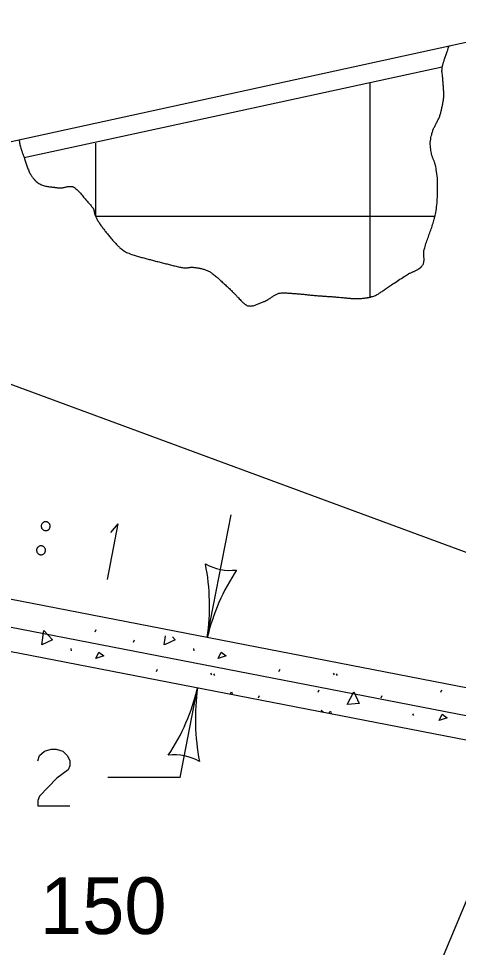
# Model space of a CAD drawing. Extents: x 49991.4 to 50043, y 49987.6 to 50011.4.
# Drawn here: x 50038.895 to 50039.361, y 49997.154 to 49998.137 of the extents above; entities that cross this region are included whole.
import ezdxf

# ---------------------------------------------------------------- set-up
doc = ezdxf.new("R2010")
doc.units = 0
for name, color, linetype in [('Level 1', 7, 'Continuous'), ('Level 2', 7, 'Continuous'), ('Level 3', 7, 'Continuous')]:
    doc.layers.add(name, color=color, linetype=linetype)

msp = doc.modelspace()

# ---------------------------------------------------------------- linework, layer by layer
at = {"layer": 'Level 1'}
for p, q in [((50038.66184, 49997.95822), (50039.48364, 49998.13732)), ((50039.34353, 49998.08582), (50038.90144, 49997.98982)), ((50039.26714, 49998.06922), (50039.26714, 49997.84252)), ((50038.97674, 49998.00562), (50038.97674, 49997.92812)), ((50038.97674, 49997.92812), (50039.33574, 49997.92812)), ((50039.48364, 49997.52972), (50038.58314, 49997.86252)), ((50039.48364, 49997.40692), (50038.66184, 49997.56632)), ((50038.61974, 49997.54532), (50039.48364, 49997.3773)), ((50038.77334, 49997.48952), (50039.37054, 49997.37372)), ((50038.91984, 49997.47452), (50038.92194, 49997.48982)), ((50038.92194, 49997.48982), (50038.93144, 49997.47992)), ((50038.97654, 49997.48822), (50038.97754, 49997.49062)), ((50038.93144, 49997.47992), (50038.92004, 49997.47462)), ((50039.01704, 49997.47732), (50039.01804, 49997.47972)), ((50039.04944, 49997.47452), (50039.05074, 49997.48422)), ((50039.06104, 49997.47992), (50039.04964, 49997.47462)), ((50039.05814, 49997.48302), (50039.06104, 49997.47992)), ((50038.95074, 49997.47062), (50038.95104, 49997.46822)), ((50038.97704, 49997.46022), (50038.98024, 49997.46692)), ((50038.98024, 49997.46692), (50038.98554, 49997.46292)), ((50039.08034, 49997.47062), (50039.08064, 49997.46822)), ((50039.10664, 49997.46022), (50039.10984, 49997.46692)), ((50039.10984, 49997.46692), (50039.11514, 49997.46292)), ((50038.98554, 49997.46292), (50038.97704, 49997.46022)), ((50039.11514, 49997.46292), (50039.10664, 49997.46022)), ((50039.04124, 49997.44642), (50039.04234, 49997.44882)), ((50039.17084, 49997.44642), (50039.17194, 49997.44882)), ((50039.09854, 49997.44442), (50039.09964, 49997.44282)), ((50039.10164, 49997.44382), (50039.10264, 49997.44222)), ((50039.22814, 49997.44442), (50039.22924, 49997.44282)), ((50039.23124, 49997.44382), (50039.23224, 49997.44222)), ((50039.21244, 49997.42462), (50039.21344, 49997.42702)), ((50039.34204, 49997.42462), (50039.34314, 49997.42702)), ((50039.11924, 49997.42242), (50039.12054, 49997.42492)), ((50039.12054, 49997.42492), (50039.12184, 49997.42192)), ((50039.14924, 49997.41852), (50039.15034, 49997.42092)), ((50039.24294, 49997.41132), (50039.25014, 49997.42492)), ((50039.25014, 49997.42492), (50039.25574, 49997.41242)), ((50039.27894, 49997.41852), (50039.27994, 49997.42092)), ((50039.25574, 49997.41242), (50039.24324, 49997.41132)), ((50039.21564, 49997.40492), (50039.21584, 49997.40372)), ((50039.21764, 49997.40332), (50039.21564, 49997.40492)), ((50039.31224, 49997.40152), (50039.31324, 49997.39992)), ((50039.34014, 49997.39452), (50039.34334, 49997.40122)), ((50039.34864, 49997.39722), (50039.34014, 49997.39452)), ((50039.34334, 49997.40122), (50039.34864, 49997.39722))]:
    msp.add_line(p, q, dxfattribs=at)
msp.add_arc((50039.22513, 49997.40249), 0.00126, 318.78601, 199.26618, dxfattribs=at)
msp.add_open_spline([(50038.89596, 49998.00924), (50038.89625, 49998.00747), (50038.89655, 49998.00569), (50038.89684, 49998.00392), (50038.89725, 49998.00149), (50038.89796, 49997.99911), (50038.89882, 49997.9968), (50038.89926, 49997.99564), (50038.8997, 49997.99448), (50038.90013, 49997.99331), (50038.90057, 49997.99215), (50038.90101, 49997.99099), (50038.90144, 49997.98982), (50038.90222, 49997.98774), (50038.90282, 49997.9856), (50038.90353, 49997.98349), (50038.90423, 49997.98142), (50038.90496, 49997.97936), (50038.90572, 49997.9773), (50038.9065, 49997.97521), (50038.90754, 49997.97324), (50038.90872, 49997.97134), (50038.90934, 49997.97034), (50038.91001, 49997.96939), (50038.91075, 49997.96848), (50038.91113, 49997.96801), (50038.91153, 49997.96755), (50038.91193, 49997.96709), (50038.91235, 49997.96661), (50038.91279, 49997.96616), (50038.91324, 49997.96572), (50038.91488, 49997.96414), (50038.91671, 49997.96286), (50038.91879, 49997.96187), (50038.92074, 49997.96093), (50038.92274, 49997.96027), (50038.92484, 49997.95993), (50038.92693, 49997.95959), (50038.92903, 49997.95926), (50038.93114, 49997.95901), (50038.93219, 49997.95889), (50038.93325, 49997.95878), (50038.93431, 49997.95866), (50038.93535, 49997.95854), (50038.9364, 49997.95834), (50038.93744, 49997.95822), (50038.93893, 49997.95805), (50038.94044, 49997.95816), (50038.94192, 49997.95837), (50038.94349, 49997.95858), (50038.945, 49997.95907), (50038.94655, 49997.95932), (50038.94802, 49997.95956), (50038.94952, 49997.95971), (50038.951, 49997.95973), (50038.9517, 49997.95973), (50038.95238, 49997.95956), (50038.95306, 49997.9593), (50038.95376, 49997.95903), (50038.95439, 49997.9587), (50038.95494, 49997.95822), (50038.95704, 49997.9564), (50038.95899, 49997.95454), (50038.96076, 49997.95246), (50038.9625, 49997.95042), (50038.96419, 49997.94835), (50038.96594, 49997.94632), (50038.9673, 49997.94475), (50038.96867, 49997.9432), (50038.97003, 49997.94164), (50038.97139, 49997.94008), (50038.97268, 49997.93848), (50038.97394, 49997.93682), (50038.9744, 49997.93622), (50038.97475, 49997.93554), (50038.97496, 49997.93481), (50038.97516, 49997.93407), (50038.97533, 49997.93332), (50038.9755, 49997.93257), (50038.97566, 49997.93181), (50038.97579, 49997.93104), (50038.97596, 49997.93028), (50038.97613, 49997.92953), (50038.9764, 49997.92881), (50038.97674, 49997.92812), (50038.97857, 49997.92442), (50038.98068, 49997.92098), (50038.98307, 49997.91765), (50038.9855, 49997.91428), (50038.988, 49997.91102), (50038.99064, 49997.90782), (50038.99387, 49997.9039), (50038.99724, 49997.90018), (50039.00081, 49997.89654), (50039.00255, 49997.89478), (50039.00444, 49997.89325), (50039.00652, 49997.89187), (50039.00858, 49997.8905), (50039.01072, 49997.88932), (50039.01304, 49997.88852), (50039.01754, 49997.88697), (50039.02204, 49997.88552), (50039.02663, 49997.88431), (50039.0312, 49997.88311), (50039.03577, 49997.8819), (50039.04034, 49997.88072), (50039.04517, 49997.87948), (50039.04999, 49997.87824), (50039.05482, 49997.87701), (50039.05964, 49997.87578), (50039.06443, 49997.87467), (50039.06934, 49997.87362), (50039.07021, 49997.87344), (50039.07109, 49997.87336), (50039.07196, 49997.87344), (50039.07285, 49997.87352), (50039.07374, 49997.87362), (50039.07462, 49997.87374), (50039.07551, 49997.87385), (50039.0764, 49997.874), (50039.07729, 49997.8741), (50039.07817, 49997.8742), (50039.07906, 49997.87419), (50039.07994, 49997.87412), (50039.08172, 49997.87398), (50039.08347, 49997.8737), (50039.08523, 49997.87341), (50039.087, 49997.87311), (50039.08873, 49997.87275), (50039.09046, 49997.87226), (50039.09393, 49997.87127), (50039.09726, 49997.86982), (50039.10014, 49997.86762), (50039.10392, 49997.86474), (50039.10743, 49997.86173), (50039.11086, 49997.85853), (50039.11421, 49997.85541), (50039.11757, 49997.85232), (50039.12084, 49997.84912), (50039.12206, 49997.84793), (50039.12327, 49997.84673), (50039.12445, 49997.8455), (50039.12565, 49997.84427), (50039.12677, 49997.84297), (50039.12795, 49997.84173), (50039.12971, 49997.83987), (50039.13149, 49997.83805), (50039.13339, 49997.83633), (50039.1337, 49997.83604), (50039.13403, 49997.83578), (50039.13435, 49997.83551), (50039.13468, 49997.83524), (50039.13499, 49997.83498), (50039.13534, 49997.83472), (50039.13671, 49997.83373), (50039.13838, 49997.83323), (50039.13997, 49997.83316), (50039.14173, 49997.83309), (50039.14359, 49997.83338), (50039.1453, 49997.834), (50039.14893, 49997.83533), (50039.15244, 49997.83668), (50039.15594, 49997.83822), (50039.15668, 49997.83854), (50039.15741, 49997.83885), (50039.15811, 49997.83923), (50039.15884, 49997.83961), (50039.15953, 49997.84005), (50039.16022, 49997.84051), (50039.16163, 49997.84143), (50039.16296, 49997.84244), (50039.16436, 49997.84338), (50039.16572, 49997.84429), (50039.16707, 49997.84511), (50039.16859, 49997.84585), (50039.17004, 49997.84655), (50039.17159, 49997.8469), (50039.17314, 49997.84692), (50039.17713, 49997.84697), (50039.18113, 49997.84688), (50039.1851, 49997.84655), (50039.18909, 49997.84621), (50039.19308, 49997.84589), (50039.19707, 49997.84551), (50039.20107, 49997.84512), (50039.20505, 49997.84463), (50039.20905, 49997.8443), (50039.21305, 49997.84397), (50039.21705, 49997.8437), (50039.22104, 49997.84342), (50039.22296, 49997.84329), (50039.22489, 49997.84322), (50039.2268, 49997.84304), (50039.22873, 49997.84286), (50039.23065, 49997.84269), (50039.23258, 49997.84251), (50039.23643, 49997.84215), (50039.24028, 49997.84179), (50039.24413, 49997.84144), (50039.24796, 49997.84108), (50039.25183, 49997.84104), (50039.25567, 49997.84113), (50039.25759, 49997.84118), (50039.2595, 49997.84132), (50039.26142, 49997.84156), (50039.26238, 49997.84168), (50039.26333, 49997.8418), (50039.26428, 49997.84197), (50039.26476, 49997.84205), (50039.26524, 49997.84214), (50039.26571, 49997.84222), (50039.26619, 49997.84231), (50039.26667, 49997.84241), (50039.26714, 49997.84252), (50039.27108, 49997.84346), (50039.27481, 49997.84525), (50039.27819, 49997.84749), (50039.28162, 49997.84976), (50039.28493, 49997.85215), (50039.28834, 49997.85442), (50039.29435, 49997.85842), (50039.30033, 49997.86245), (50039.30644, 49997.86632), (50039.30768, 49997.8671), (50039.30899, 49997.86775), (50039.31032, 49997.86837), (50039.31165, 49997.869), (50039.31302, 49997.8695), (50039.31436, 49997.87012), (50039.3157, 49997.87074), (50039.31701, 49997.87139), (50039.31829, 49997.87214), (50039.31894, 49997.87252), (50039.31954, 49997.87296), (50039.32013, 49997.87344), (50039.32043, 49997.87368), (50039.32072, 49997.87393), (50039.32101, 49997.87419), (50039.3213, 49997.87445), (50039.32157, 49997.87472), (50039.32184, 49997.87502), (50039.32289, 49997.8762), (50039.32366, 49997.87758), (50039.32396, 49997.87912), (50039.32425, 49997.88068), (50039.32432, 49997.88223), (50039.32427, 49997.8838), (50039.32423, 49997.88542), (50039.32407, 49997.88704), (50039.32405, 49997.88867), (50039.32404, 49997.88946), (50039.32406, 49997.89025), (50039.32413, 49997.89104), (50039.3242, 49997.89182), (50039.32432, 49997.89258), (50039.32454, 49997.89332), (50039.3254, 49997.89624), (50039.32631, 49997.89912), (50039.32733, 49997.90197), (50039.32834, 49997.90484), (50039.32939, 49997.9077), (50039.3304, 49997.91057), (50039.33142, 49997.91345), (50039.33238, 49997.91634), (50039.33335, 49997.91924), (50039.33432, 49997.92215), (50039.33506, 49997.92509), (50039.33574, 49997.92812), (50039.33755, 49997.93611), (50039.33827, 49997.94417), (50039.33854, 49997.95222), (50039.33885, 49997.9615), (50039.33834, 49997.97085), (50039.33674, 49997.98012), (50039.33651, 49997.98146), (50039.33625, 49997.98278), (50039.33579, 49997.98405), (50039.33532, 49997.98532), (50039.33485, 49997.9866), (50039.33437, 49997.98787), (50039.3339, 49997.98914), (50039.33342, 49997.9904), (50039.33295, 49997.99167), (50039.33248, 49997.99291), (50039.33218, 49997.99422), (50039.33194, 49997.99552), (50039.33071, 49998.00238), (50039.33107, 49998.00969), (50039.33294, 49998.01652), (50039.33343, 49998.01829), (50039.33401, 49998.02001), (50039.33482, 49998.02163), (50039.33565, 49998.02327), (50039.33648, 49998.0249), (50039.33731, 49998.02653), (50039.33813, 49998.02817), (50039.33896, 49998.02981), (50039.33978, 49998.03145), (50039.3406, 49998.03309), (50039.34116, 49998.03485), (50039.34164, 49998.03662), (50039.34216, 49998.03851), (50039.34261, 49998.04041), (50039.34305, 49998.04231), (50039.34349, 49998.04421), (50039.34391, 49998.04609), (50039.34426, 49998.04802), (50039.34497, 49998.05185), (50039.34534, 49998.05569), (50039.34514, 49998.05952), (50039.34492, 49998.06375), (50039.34452, 49998.06799), (50039.34424, 49998.07222), (50039.34395, 49998.07678), (50039.34304, 49998.08138), (50039.34354, 49998.08592), (50039.3436, 49998.08641), (50039.34378, 49998.08689), (50039.34391, 49998.08737), (50039.34404, 49998.08785), (50039.34417, 49998.08833), (50039.3443, 49998.0888), (50039.34457, 49998.08976), (50039.34484, 49998.09071), (50039.34514, 49998.09166), (50039.34574, 49998.09354), (50039.34637, 49998.09542), (50039.347, 49998.09729), (50039.34825, 49998.10099), (50039.34959, 49998.10466), (50039.35079, 49998.10837)], degree=3, dxfattribs=at)
at = {"layer": 'Level 2'}
for q in [(50038.98904, 49997.54357), (50038.99271, 49997.5934)]:
    msp.add_line((50039.00049, 49997.60247), q, dxfattribs=at)
for points in [[(50038.92874, 49997.5992), (50038.92881, 49997.5997), (50038.92883, 49997.60019), (50038.92879, 49997.60069), (50038.92871, 49997.60117), (50038.92857, 49997.60165), (50038.92839, 49997.60211), (50038.92815, 49997.60254), (50038.92788, 49997.60295), (50038.92756, 49997.60333), (50038.9272, 49997.60367), (50038.92682, 49997.60398), (50038.9264, 49997.60424), (50038.92595, 49997.60445), (50038.92549, 49997.60463), (50038.92501, 49997.60475), (50038.92452, 49997.60482), (50038.92403, 49997.60483), (50038.92353, 49997.6048), (50038.92304, 49997.60471), (50038.92257, 49997.60458), (50038.92211, 49997.60439), (50038.92167, 49997.60416), (50038.92126, 49997.60388), (50038.92089, 49997.60357), (50038.92054, 49997.60321), (50038.92023, 49997.60282), (50038.91997, 49997.6024), (50038.91976, 49997.60196), (50038.91959, 49997.60149), (50038.91947, 49997.60101), (50038.9194, 49997.60052), (50038.91938, 49997.60002), (50038.91941, 49997.59953), (50038.9195, 49997.59905), (50038.91964, 49997.59857), (50038.91982, 49997.59811), (50038.92005, 49997.59768), (50038.92033, 49997.59726), (50038.92065, 49997.59689), (50038.92101, 49997.59654), (50038.92139, 49997.59624), (50038.92181, 49997.59598), (50038.92226, 49997.59576), (50038.92272, 49997.59559), (50038.92321, 49997.59547), (50038.92369, 49997.5954), (50038.92419, 49997.59539), (50038.92468, 49997.59542), (50038.92517, 49997.5955), (50038.92564, 49997.59564), (50038.9261, 49997.59583), (50038.92654, 49997.59606), (50038.92695, 49997.59634), (50038.92733, 49997.59665), (50038.92767, 49997.59701), (50038.92798, 49997.5974), (50038.92824, 49997.59782), (50038.92846, 49997.59826), (50038.92862, 49997.59873), (50038.92874, 49997.5992)], [(50038.92379, 49997.5737), (50038.92385, 49997.57419), (50038.92387, 49997.57468), (50038.92384, 49997.57518), (50038.92375, 49997.57566), (50038.92361, 49997.57614), (50038.92343, 49997.5766), (50038.9232, 49997.57703), (50038.92292, 49997.57744), (50038.9226, 49997.57783), (50038.92224, 49997.57816), (50038.92186, 49997.57847), (50038.92144, 49997.57873), (50038.921, 49997.57895), (50038.92053, 49997.57912), (50038.92005, 49997.57924), (50038.91956, 49997.57931), (50038.91907, 49997.57933), (50038.91857, 49997.57929), (50038.91808, 49997.57921), (50038.91761, 49997.57907), (50038.91715, 49997.57889), (50038.91671, 49997.57865), (50038.9163, 49997.57837), (50038.91593, 49997.57806), (50038.91558, 49997.5777), (50038.91527, 49997.57731), (50038.91501, 49997.57689), (50038.9148, 49997.57645), (50038.91463, 49997.57598), (50038.91451, 49997.5755), (50038.91444, 49997.57501), (50038.91443, 49997.57452), (50038.91446, 49997.57402), (50038.91454, 49997.57354), (50038.91468, 49997.57306), (50038.91487, 49997.57261), (50038.9151, 49997.57217), (50038.91537, 49997.57176), (50038.9157, 49997.57138), (50038.91605, 49997.57104), (50038.91643, 49997.57073), (50038.91685, 49997.57047), (50038.9173, 49997.57025), (50038.91776, 49997.57008), (50038.91825, 49997.56997), (50038.91873, 49997.56989), (50038.91923, 49997.56988), (50038.91972, 49997.56991), (50038.92021, 49997.57), (50038.92068, 49997.57013), (50038.92115, 49997.57032), (50038.92158, 49997.57055), (50038.92199, 49997.57083), (50038.92237, 49997.57115), (50038.92271, 49997.5715), (50038.92302, 49997.57189), (50038.92328, 49997.57231), (50038.9235, 49997.57276), (50038.92366, 49997.57322), (50038.92379, 49997.5737)], [(50038.91564, 49997.35174), (50038.91753, 49997.35741), (50038.92273, 49997.36213), (50038.92982, 49997.36402), (50038.93502, 49997.36402), (50038.9421, 49997.36213), (50038.9473, 49997.35693), (50038.94966, 49997.35174), (50038.94966, 49997.34654), (50038.94777, 49997.34229), (50038.93596, 49997.33331), (50038.91753, 49997.31441), (50038.91564, 49997.30969), (50038.91564, 49997.30402), (50038.94966, 49997.30402)]]:
    msp.add_lwpolyline(points, dxfattribs=at)
at = {"layer": 'Level 3'}
for p, q in [((50039.09502, 49997.4823), (50039.12033, 49997.6121)), ((50039.06634, 49997.33402), (50039.08475, 49997.42914)), ((50039.06634, 49997.33402), (50038.98964, 49997.33402)), ((50039.41923, 49997.32489), (50039.31754, 49997.08002))]:
    msp.add_line(p, q, dxfattribs=at)
for centre, radius, start, end in [((50039.11956, 49997.60814), 0.05477, 241.10324, 276.8256), ((50038.86441, 49997.51557), 0.233, 351.79173, 11.04158), ((50039.31129, 49997.43079), 0.22232, 146.42043, 166.60394), ((50038.8684, 49997.48032), 0.22232, 326.50569, 346.6892), ((50039.31541, 49997.39622), 0.233, 171.87699, 191.12684), ((50039.06039, 49997.30326), 0.05477, 61.1885, 96.91086)]:
    msp.add_arc(centre, radius, start, end, dxfattribs=at)

# ---------------------------------------------------------------- texts
at = {"layer": 'Level 2'}
msp.add_text('150', height=0.06, dxfattribs=at).set_placement((50038.91804, 49997.16852))

doc.saveas('drawing.dxf')
